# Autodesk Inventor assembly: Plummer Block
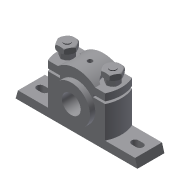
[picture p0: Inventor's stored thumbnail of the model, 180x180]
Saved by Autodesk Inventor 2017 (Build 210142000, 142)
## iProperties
Created: 2011-07
Part Number: Plummer Block
Document SubType Name: Assembly
Designer: CadCim
Author: CadCim
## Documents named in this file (7)
- D:\KAVITA\Autodesk Inventor_2017_Project\Part's File\Inventor_2016_tut\c09_Inv_tut_2016\c09_tut02_inv\Plummer Block\Plummer Block.iam
- D:\KAVITA\Autodesk Inventor_2017_Project\Part's File\Inventor_2016_tut\c09_Inv_tut_2016\c09_tut02_inv\Plummer Block\Casting.ipt
- D:\KAVITA\Autodesk Inventor_2017_Project\Part's File\Inventor_2016_tut\c09_Inv_tut_2016\c09_tut02_inv\Plummer Block\Brasses.ipt
- D:\KAVITA\Autodesk Inventor_2017_Project\Part's File\Inventor_2016_tut\c09_Inv_tut_2016\c09_tut02_inv\Plummer Block\Cap.ipt
- D:\KAVITA\Autodesk Inventor_2017_Project\Part's File\Inventor_2016_tut\c09_Inv_tut_2016\c09_tut02_inv\Plummer Block\Bolt.ipt
- D:\KAVITA\Autodesk Inventor_2017_Project\Part's File\Inventor_2016_tut\c09_Inv_tut_2016\c09_tut02_inv\Plummer Block\Nut.ipt
- D:\KAVITA\Autodesk Inventor_2017_Project\Part's File\Inventor_2016_tut\c09_Inv_tut_2016\c09_tut02_inv\Plummer Block\Lock Nut.ipt
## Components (9 placed, 6 different names)
1. Casting:1 — Mate:1, Mate:2, Insert:1, Angle:1, Insert:2, Angle:2
2. Brasses:1 — Mate:1, Mate:2, Mate:3, Mate:4
3. Cap:1 — Mate:3, Mate:4, Insert:4, Insert:5
4. Bolt:1 — Insert:1, Angle:1
5. Bolt:2 — Insert:2, Angle:2
6. Nut:2 — Insert:4, Insert:7
7. Nut:3 — Insert:5, Insert:6
8. Lock Nut:3 — Insert:6
9. Lock Nut:4 — Insert:7
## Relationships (12: Insert 6, Mate 4, Angle 2)
- Mate:1: Casting:1 ↔ Brasses:1
- Mate:2: Casting:1 ↔ Brasses:1
- Mate:3: Brasses:1 ↔ Cap:1
- Mate:4: Brasses:1 ↔ Cap:1
- Insert:1: Casting:1 ↔ Bolt:1
- Angle:1: Casting:1 ↔ Bolt:1
- Insert:2: Casting:1 ↔ Bolt:2
- Angle:2: Casting:1 ↔ Bolt:2
- Insert:4: Cap:1 ↔ Nut:2
- Insert:5: Cap:1 ↔ Nut:3
- Insert:6: Nut:3 ↔ Lock Nut:3
- Insert:7: Nut:2 ↔ Lock Nut:4
